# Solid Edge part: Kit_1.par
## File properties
Sűrűség: 0,000 kg/m^3
Pontosság: 0,990
Author: psaghy
Last saved by: psaghy
Revision: 79
Username: psaghy
Dokumentum tartalom típus: 0
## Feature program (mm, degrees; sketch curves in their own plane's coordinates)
base feature "unnamed BaseFeature 1"
sketch for "Furat_1" plane through (0, -41.625, 7) normal (0, 0, 1) x-axis (0, 1, 0)
  hole centre (0.625, 0) bore radius 2.067
hole "Furat_1" finite
chamfer "Letörés_1" setback 0.5
thread "unnamed Thread 1"
chamfer "Letörés_2" setback 1
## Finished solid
Body 1: solid body, 47 faces, 49 edges, 4 vertices.
  Faces by surface: plane 16, cylinder 13, cone 11, torus 7
  Edges by curve: circle 45, line 4
Bounding box of the edges (mm; curved faces can reach further): 16.000 x 22.250 x 15.000, from (-8, -58, -8) to (8, -35.75, 7).
Cylindrical faces by radius (mm): R2.067 x1, R2.213 x1, R2.35 x1, R3.25 x1, R3.3 x1, R3.35 x1, R4.05 x1, R4.1 x1, R4.6 x1, R5 x1, R6 x2, R8 x1
Conical faces (half-angle, radius in mm at the cone's reference point): 5.7574 deg R3.25 x1, 12.9869 deg R2.0077 x1, 14.7799 deg R2.7245 x1, 15 deg R4.05 x1, 16.6443 deg R2.35 x1, 20.502 deg R2.513 x1, 45 deg R2.067 x1, 45 deg R3.4 x1, 45 deg R3.5 x1, 45 deg R6 x1, 60 deg R5.5 x1
Toroidal faces (ring radius, tube radius in mm): R2.2 r0.2 x1, R2.3 r0.3 x1, R2.9179 r0.2 x1, R3.1 r0.2 x1, R3.85 r0.2 x1, R4.09 r0.01 x2
Planar faces by outward normal: +y 5, +z 2, -y 9
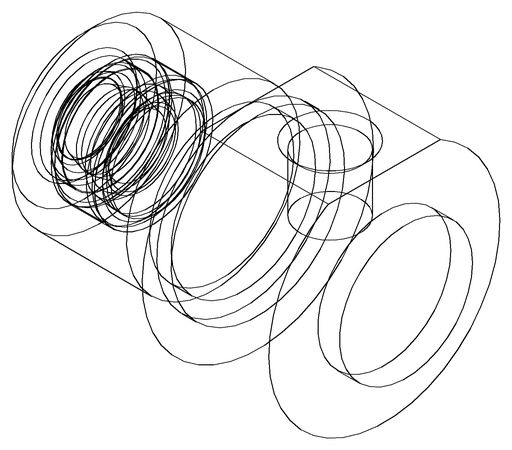
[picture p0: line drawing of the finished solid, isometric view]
